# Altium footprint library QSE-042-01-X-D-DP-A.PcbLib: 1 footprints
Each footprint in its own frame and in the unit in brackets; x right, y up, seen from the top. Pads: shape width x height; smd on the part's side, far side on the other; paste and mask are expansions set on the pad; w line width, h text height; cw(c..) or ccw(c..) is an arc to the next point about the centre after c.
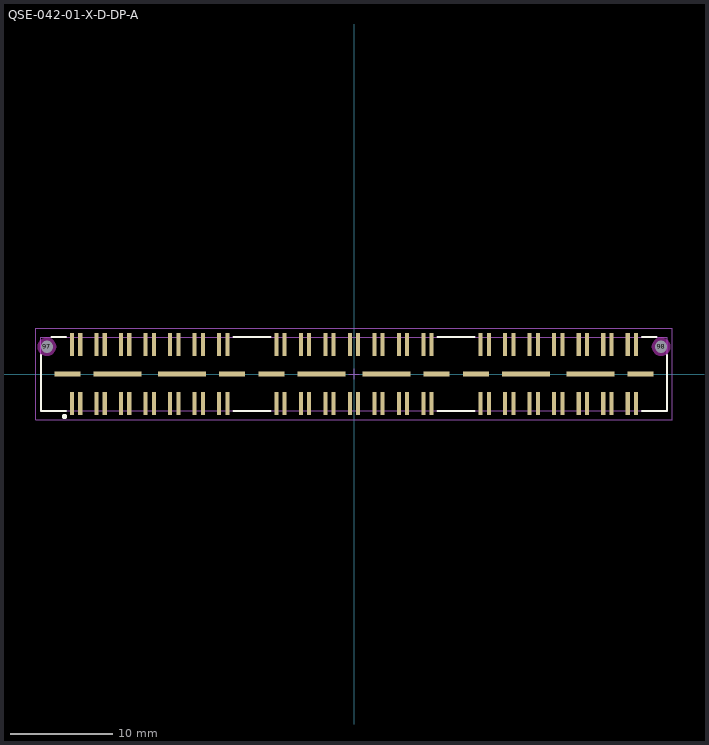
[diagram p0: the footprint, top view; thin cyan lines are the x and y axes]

## QSE-042-01-X-D-DP-A [mm] "0.80mm pitch, 84 pin, high speed socket strip; differential"
height 3.25
pads (98):
  rect 0.4x2.25 smd mask+0: 1(-27.6,-2.87) 2(-27.6,2.87) 3(-26.8,-2.87) 4(-26.8,2.87) 5(-25.2,-2.87) 6(-25.2,2.87) 7(-24.4,-2.87) 8(-24.4,2.87) 9(-22.8,-2.87) 10(-22.8,2.87) 11(-22,-2.87) 12(-22,2.87) 13(-20.4,-2.87) 14(-20.4,2.87) 15(-19.6,-2.87) 16(-19.6,2.87) 17(-18,-2.87) 18(-18,2.87) 19(-17.2,-2.87) 20(-17.2,2.87) 21(-15.6,-2.87) 22(-15.6,2.87) 23(-14.8,-2.87) 24(-14.8,2.87) 25(-13.2,-2.87) 26(-13.2,2.87) 27(-12.4,-2.87) 28(-12.4,2.87) 29(-7.6,-2.87) 30(-7.6,2.87) 31(-6.8,-2.87) 32(-6.8,2.87) 33(-5.2,-2.87) 34(-5.2,2.87) 35(-4.4,-2.87) 36(-4.4,2.87) 37(-2.8,-2.87) 38(-2.8,2.87) 39(-2,-2.87) 40(-2,2.87) 41(-0.4,-2.87) 42(-0.4,2.87) 43(0.4,-2.87) 44(0.4,2.87) 45(2,-2.87) 46(2,2.87) 47(2.8,-2.87) 48(2.8,2.87) 49(4.4,-2.87) 50(4.4,2.87) 51(5.2,-2.87) 52(5.2,2.87) 53(6.8,-2.87) 54(6.8,2.87) 55(7.6,-2.87) 56(7.6,2.87) 57(12.4,-2.87) 58(12.4,2.87) 59(13.2,-2.87) 60(13.2,2.87) 61(14.8,-2.87) 62(14.8,2.87) 63(15.6,-2.87) 64(15.6,2.87) 65(17.2,-2.87) 66(17.2,2.87) 67(18,-2.87) 68(18,2.87) 69(19.6,-2.87) 70(19.6,2.87) 71(20.4,-2.87) 72(20.4,2.87) 73(22,-2.87) 74(22,2.87) 75(22.8,-2.87) 76(22.8,2.87) 77(24.4,-2.87) 78(24.4,2.87) 79(25.2,-2.87) 80(25.2,2.87) 81(26.8,-2.87) 82(26.8,2.87) 83(27.6,-2.87) 84(27.6,2.87)
  rect 2.55x0.45 smd mask+0: 85(-28.065,0) 88(-11.935,0) 89(-8.065,0) 92(8.065,0) 93(11.935,0) 96(28.065,0)
  rect 4.7x0.45 smd mask+0: 86(-23.175,0) 87(-16.825,0) 90(-3.175,0) 91(3.175,0) 94(16.825,0) 95(23.175,0)
  round 1 hole 1.2 unplated mask+0: 97(-30.065,2.67) 98(30.065,2.67)
Top Overlay:
  circle w0.25: c-28.35,-4.15 r0.125
  lines w0.2: -30.65,1.85 -30.65,-3.6 -28.2,-3.6 ; -29.6,3.6 -28.2,3.6 ; -11.8,-3.6 -8.2,-3.6 ; -11.8,3.6 -8.2,3.6 ; 8.2,-3.6 11.8,-3.6 ; 8.2,3.6 11.8,3.6 ; 28.2,-3.6 30.65,-3.6 30.65,1.85 ; 28.2,3.6 29.6,3.6
Keep-Out Layer:
  pour cut-out: 30.973,2.67 30.942,2.905 30.851,3.124 30.707,3.312 30.519,3.456 30.3,3.547 30.065,3.578 29.83,3.547 29.611,3.456 29.423,3.312 29.279,3.124 29.188,2.905 29.157,2.67 29.188,2.435 29.279,2.216 29.423,2.028 29.611,1.884 29.83,1.793 30.065,1.762 30.3,1.793 30.519,1.884 30.707,2.028 30.851,2.216 30.942,2.435
  pour cut-out: -29.157,2.67 -29.188,2.905 -29.279,3.124 -29.423,3.312 -29.611,3.456 -29.83,3.547 -30.065,3.578 -30.3,3.547 -30.519,3.456 -30.707,3.312 -30.851,3.124 -30.942,2.905 -30.973,2.67 -30.942,2.435 -30.851,2.216 -30.707,2.028 -30.519,1.884 -30.3,1.793 -30.065,1.762 -29.83,1.793 -29.611,1.884 -29.423,2.028 -29.279,2.216 -29.188,2.435
Mechanical 12:
  lines w0.001: -30.65,-3.6 -30.65,3.6 30.65,3.6 30.65,-3.6 -30.65,-3.6
Mechanical 13:
  circle w0.25: c-28.35,-4.15 r0.125
  lines w0.1: -30.65,-3.6 -30.65,3.6 30.65,3.6 30.65,-3.6 -30.65,-3.6
  text ".Designator" at 0.254,0.254 h1.52
Mechanical 15:
  lines w0.05: -0.5,0 0.5,0 ; 0,-0.5 0,0.5 ; -31.15,-4.5 -31.15,4.5 31.15,4.5 31.15,-4.5 -31.15,-4.5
